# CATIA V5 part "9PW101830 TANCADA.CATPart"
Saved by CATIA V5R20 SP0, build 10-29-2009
Part number: 9PW101830 TANCADA
Revision: ANY
Definition: UNKNOWN
Nomenclature: 9PW101830 TANCADA
Source: Unknown
Bounding box of the stored display mesh (mm): x -175 to 0, y -8.113 to 5.5, z -9.1 to 9.1
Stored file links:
  C:\Users\Utente\Desktop\IO LAVORO\3D X SITO CF\CUMSA\3D files PW\pw101830\pw101830_injection\9PW101830 TANCADA.CATPart
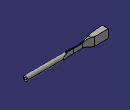
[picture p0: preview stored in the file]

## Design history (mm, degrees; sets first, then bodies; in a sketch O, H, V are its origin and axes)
Body1 "Chaflán5" (main body)
  Solid1: solid without history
